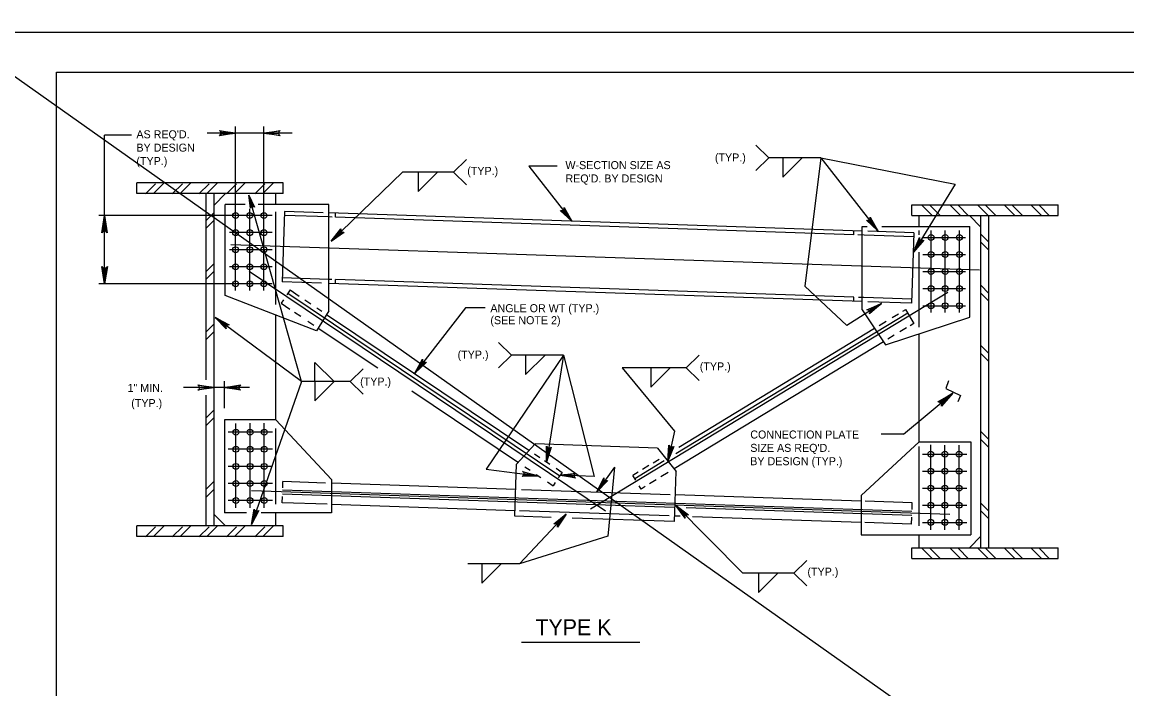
# Model space of a CAD drawing. Extents: x 634656 to 641360, y 298715 to 301183.
# Drawn here: x 635534.5 to 635948.6, y 300260.9 to 300510.8 of the extents above; entities that cross this region are included whole.
import ezdxf

# ---------------------------------------------------------------- set-up
doc = ezdxf.new("R2010")
doc.units = 0
for name, color, linetype in [('1', 7, 'Continuous'), ('2', 7, 'Continuous'), ('PLT-BNDY', 7, 'Continuous')]:
    doc.layers.add(name, color=color, linetype=linetype)

msp = doc.modelspace()

# ---------------------------------------------------------------- linework, layer by layer
at = {"layer": '1'}
for p, q in [((635502.92, 300510.77), (636362.53, 299902.94)), ((635614.56, 300410.14), (635614.56, 300471.64)), ((635625.18, 300410.14), (635625.18, 300471.64)), ((635565.46, 300438.26), (635565.46, 300468.36)), ((635833.84, 300459.87), (635814.41, 300459.87)), ((635833.84, 300459.87), (635827.91, 300411.87)), ((635833.84, 300459.87), (635855.28, 300432.5)), ((635833.84, 300459.87), (635884.2, 300450.08)), ((635677.12, 300454.5), (635650.4, 300428.64)), ((635724.42, 300456.73), (635740.53, 300436.16)), ((635632.4, 300450.49), (635577.59, 300450.49)), ((635577.59, 300446.49), (635577.59, 300450.49)), ((635584.56, 300450.21), (635580.75, 300446.4)), ((635587.76, 300450.49), (635583.77, 300446.49)), ((635594.6, 300450.21), (635590.78, 300446.4)), ((635597.8, 300450.49), (635593.8, 300446.49)), ((635604.63, 300450.21), (635600.82, 300446.4)), ((635607.83, 300450.49), (635603.83, 300446.49)), ((635614.9, 300450.21), (635611.09, 300446.4)), ((635618.1, 300450.49), (635614.11, 300446.49)), ((635625.51, 300450.21), (635621.7, 300446.4)), ((635628.71, 300450.49), (635624.71, 300446.49)), ((635632.4, 300446.49), (635632.4, 300450.49)), ((635884.2, 300450.08), (635868.61, 300424.55)), ((635632.4, 300446.49), (635577.59, 300446.49)), ((635603.5, 300376.66), (635603.5, 300446.49)), ((635606.5, 300321.96), (635606.5, 300446.49)), ((635606.5, 300442.17), (635610.82, 300446.49)), ((635639.27, 300376.12), (635619.55, 300445.94)), ((635629.64, 300442.37), (635629.64, 300446.49)), ((635610.61, 300408.38), (635610.61, 300442.37)), ((635618.17, 300442.37), (635610.61, 300442.37)), ((635649.52, 300442.37), (635623.07, 300442.37)), ((635649.52, 300402.59), (635649.52, 300442.37)), ((635867.97, 300442.3), (635922.79, 300442.3)), ((635867.97, 300438.3), (635867.97, 300442.3)), ((635871.67, 300442.3), (635875.66, 300438.3)), ((635874.87, 300442.02), (635878.68, 300438.21)), ((635882.27, 300442.3), (635886.27, 300438.3)), ((635885.47, 300442.02), (635889.28, 300438.21)), ((635892.54, 300442.3), (635896.54, 300438.3)), ((635895.75, 300442.02), (635899.56, 300438.21)), ((635902.58, 300442.3), (635906.57, 300438.3)), ((635905.78, 300442.02), (635909.59, 300438.21)), ((635912.61, 300442.3), (635916.61, 300438.3)), ((635915.81, 300442.02), (635919.62, 300438.21)), ((635922.79, 300438.3), (635922.79, 300442.3)), ((635628.31, 300438.26), (635563.35, 300438.26)), ((635565.46, 300412.69), (635565.46, 300438.26)), ((635606.5, 300439.46), (635603.5, 300436.46)), ((635619.87, 300410.14), (635619.87, 300440.82)), ((635629.64, 300404.98), (635629.64, 300439.65)), ((635632.85, 300439.81), (635631.95, 300413.44)), ((635649.36, 300437.75), (635632.8, 300438.31)), ((635647.41, 300439.32), (635632.85, 300439.81)), ((635650.72, 300437.71), (635649.36, 300437.75)), ((635849.34, 300432.47), (635649.52, 300439.25)), ((635652.02, 300437.69), (635652.02, 300439.19)), ((635846.3, 300431.07), (635652.02, 300437.66)), ((635867.97, 300438.3), (635922.79, 300438.3)), ((635870.74, 300434.18), (635870.74, 300438.3)), ((635893.88, 300433.97), (635889.55, 300438.3)), ((635893.88, 300313.77), (635893.88, 300438.3)), ((635896.88, 300313.77), (635896.88, 300438.3)), ((635606.5, 300436.53), (635603.5, 300433.53)), ((635849.34, 300402.89), (635849.34, 300434.18)), ((635849.34, 300434.18), (635851.31, 300434.18)), ((635856.7, 300434.18), (635889.77, 300434.18)), ((635889.77, 300400.19), (635889.77, 300434.18)), ((635628.31, 300431.87), (635612.21, 300431.87)), ((635846.3, 300431.07), (635846.3, 300432.53)), ((635850.08, 300430.94), (635847.77, 300431.02)), ((635868.74, 300430.31), (635850.08, 300430.94)), ((635868.79, 300431.81), (635851.52, 300432.39)), ((635868.79, 300431.81), (635867.9, 300405.44)), ((635870.74, 300431.01), (635870.74, 300432.71)), ((635872.06, 300430.07), (635888.16, 300430.07)), ((635875.2, 300401.95), (635875.2, 300432.63)), ((635880.51, 300401.95), (635880.51, 300432.63)), ((635885.82, 300401.95), (635885.82, 300432.63)), ((635893.88, 300431.27), (635896.88, 300428.26)), ((635628.31, 300425.48), (635612.21, 300425.48)), ((635893.32, 300417.78), (635612.8, 300427.29)), ((635870.74, 300396.42), (635870.74, 300424.62)), ((635893.88, 300428.34), (635896.88, 300425.34)), ((635872.06, 300423.68), (635888.16, 300423.68)), ((635606.5, 300420.33), (635603.5, 300417.33)), ((635606.5, 300417.41), (635603.5, 300414.4)), ((635628.31, 300419.08), (635612.21, 300419.08)), ((635619.62, 300417.49), (635753.2, 300327.64)), ((635872.06, 300417.28), (635888.16, 300417.28)), ((635628.31, 300412.69), (635563.35, 300412.69)), ((635646.76, 300412.94), (635631.95, 300413.44)), ((635649.52, 300414.35), (635632, 300414.94)), ((635650.56, 300414.31), (635649.52, 300414.35)), ((635849.34, 300406.07), (635649.52, 300412.85)), ((635652.02, 300412.79), (635652.02, 300414.29)), ((635846.3, 300407.67), (635652.02, 300414.26)), ((635893.88, 300412.14), (635896.88, 300409.13)), ((635644.84, 300395.07), (635610.61, 300408.38)), ((635634.97, 300410.43), (635633.75, 300408.6)), ((635634.13, 300409.17), (635736.05, 300340.8)), ((635634.97, 300410.43), (635638.43, 300408.11)), ((635881.52, 300409.5), (635747.6, 300328.2)), ((635827.91, 300411.87), (635843.58, 300397.05)), ((635872.06, 300410.89), (635888.16, 300410.89)), ((635893.88, 300409.21), (635896.88, 300406.21)), ((635632.5, 300406.74), (635631.63, 300405.44)), ((635631.63, 300405.44), (635634.88, 300403.26)), ((635640.48, 300406.73), (635642.79, 300405.18)), ((635856.6, 300405.3), (635843.58, 300397.05)), ((635846.3, 300406.13), (635846.3, 300407.67)), ((635850.04, 300407.54), (635848.06, 300407.61)), ((635867.95, 300406.94), (635850.04, 300407.54)), ((635867.9, 300405.44), (635851.51, 300405.99)), ((635872.06, 300404.5), (635888.16, 300404.5)), ((635639.27, 300376.12), (635606.87, 300400.04)), ((635629.64, 300361.72), (635629.64, 300400.98)), ((635636.67, 300402.06), (635638.96, 300400.53)), ((635649.52, 300402.59), (635644.84, 300395.07)), ((635644.99, 300403.71), (635646.93, 300402.41)), ((635648.67, 300401.22), (635724.47, 300350.38)), ((635700.69, 300403.7), (635681.78, 300379.28)), ((635866.46, 300401.73), (635779.6, 300349.01)), ((635849.34, 300402.89), (635858.17, 300389.82)), ((635858.17, 300389.82), (635889.77, 300400.19)), ((635863.01, 300401.39), (635860.64, 300399.96)), ((635865.64, 300402.99), (635864.49, 300402.29)), ((635865.62, 300403.12), (635868.8, 300397.89)), ((635606.5, 300397.75), (635603.5, 300394.74)), ((635641.66, 300398.72), (635643.83, 300397.26)), ((635645.5, 300396.12), (635667.8, 300381.17)), ((635854.04, 300395.95), (635780.61, 300351.37)), ((635858.37, 300398.58), (635855.76, 300397)), ((635865.96, 300396.17), (635863.51, 300394.68)), ((635868.8, 300397.89), (635867.34, 300397)), ((635606.5, 300394.82), (635603.5, 300391.82)), ((635861.41, 300393.4), (635859.05, 300391.97)), ((635870.74, 300353.53), (635870.74, 300393.95)), ((635857.4, 300390.97), (635778.92, 300343.33)), ((635893.88, 300389.55), (635896.88, 300386.55)), ((635737.41, 300385.99), (635708.43, 300343.23)), ((635737.41, 300385.99), (635717.98, 300385.99)), ((635737.41, 300385.99), (635731.11, 300345.92)), ((635737.41, 300385.99), (635748.96, 300340.44)), ((635893.88, 300386.63), (635896.88, 300383.63)), ((635759.48, 300381.23), (635779.02, 300357.46)), ((635610.33, 300366.16), (635610.33, 300376.26)), ((635603.5, 300321.96), (635603.5, 300370.94)), ((635680.56, 300372.6), (635720.52, 300345.8)), ((635864.81, 300356.4), (635883.4, 300371.78)), ((635606.5, 300365.54), (635603.5, 300362.54)), ((635606.5, 300362.61), (635603.5, 300359.61)), ((635610.33, 300361.72), (635610.33, 300326.86)), ((635629.64, 300361.72), (635610.33, 300361.72)), ((635614.68, 300328.75), (635614.68, 300360.4)), ((635619.99, 300328.75), (635619.99, 300360.47)), ((635625.3, 300328.75), (635625.3, 300360.54)), ((635629.64, 300361.72), (635650.48, 300339.34)), ((635629.64, 300330.16), (635629.64, 300358.49)), ((635628.44, 300357.08), (635611.72, 300357.08)), ((635779.02, 300357.46), (635776.59, 300346.3)), ((635864.81, 300356.4), (635856.5, 300356.4)), ((635893.88, 300357.35), (635896.88, 300354.34)), ((635893.88, 300354.42), (635896.88, 300351.42)), ((635628.44, 300350.69), (635611.72, 300350.69)), ((635726.81, 300352.68), (635719.86, 300345.08)), ((635772.71, 300351.12), (635726.81, 300352.68)), ((635772.71, 300351.12), (635779.64, 300342.43)), ((635870.74, 300353.53), (635848.98, 300333.36)), ((635870.74, 300353.53), (635890.04, 300353.53)), ((635870.74, 300321.97), (635870.74, 300351.75)), ((635875.08, 300320.56), (635875.08, 300352.35)), ((635880.39, 300320.56), (635880.39, 300352.28)), ((635885.7, 300320.56), (635885.7, 300352.21)), ((635890.04, 300353.53), (635890.04, 300318.67)), ((635726.59, 300348.95), (635728.57, 300347.63)), ((635730.31, 300346.46), (635732.34, 300345.1)), ((635775.2, 300346.34), (635764.15, 300339.63)), ((635773.27, 300346.92), (635771.02, 300345.55)), ((635871.93, 300348.89), (635888.66, 300348.89)), ((635628.44, 300344.29), (635611.72, 300344.29)), ((635708.43, 300343.23), (635727.81, 300340.77)), ((635719.2, 300325.64), (635719.86, 300345.08)), ((635723, 300344.14), (635724.95, 300342.83)), ((635734.64, 300343.56), (635736.89, 300342.05)), ((635736.89, 300342.05), (635735.49, 300339.96)), ((635756.51, 300344.02), (635749.96, 300334.77)), ((635756.51, 300344.02), (635754.11, 300318.2)), ((635765.37, 300342.12), (635763.37, 300340.91)), ((635769.42, 300344.58), (635767.01, 300343.12)), ((635776.68, 300341.97), (635773.97, 300340.33)), ((635779.01, 300323.61), (635779.64, 300342.43)), ((635871.93, 300342.49), (635888.66, 300342.49)), ((635606.5, 300338.7), (635603.5, 300335.7)), ((635628.44, 300337.9), (635611.72, 300337.9)), ((635632.2, 300336.31), (635632.28, 300338.6)), ((635648.3, 300338.06), (635632.28, 300338.6)), ((635650.48, 300339.34), (635650.48, 300326.86)), ((635719.54, 300335.64), (635650.48, 300337.98)), ((635727.21, 300341.31), (635728.96, 300340.14)), ((635731.44, 300338.48), (635733.55, 300337.06)), ((635734.32, 300338.22), (635733.55, 300337.06)), ((635748.96, 300340.44), (635736.22, 300341.05)), ((635764.49, 300339.08), (635763.37, 300340.91)), ((635772.12, 300339.2), (635769.72, 300337.74)), ((635606.5, 300335.78), (635603.5, 300332.78)), ((635882.27, 300326.25), (635620.46, 300335.13)), ((635778.92, 300328.91), (635632.12, 300333.89)), ((635868.04, 300327.35), (635632.17, 300335.36)), ((635777.45, 300333.67), (635721.75, 300335.56)), ((635766.49, 300335.79), (635765.77, 300336.97)), ((635768.07, 300336.74), (635766.49, 300335.79)), ((635848.98, 300331.25), (635779.34, 300333.61)), ((635871.93, 300336.1), (635888.66, 300336.1)), ((635628.44, 300331.51), (635611.72, 300331.51)), ((635632.01, 300330.64), (635632.09, 300332.95)), ((635648.93, 300330.07), (635632.01, 300330.64)), ((635719.27, 300327.68), (635650.48, 300330.02)), ((635779.52, 300329.62), (635804.62, 300304.32)), ((635848.98, 300333.36), (635848.98, 300318.67)), ((635868.15, 300330.6), (635850.46, 300331.2)), ((635868.06, 300328.12), (635868.15, 300330.6)), ((635871.93, 300329.71), (635888.66, 300329.71)), ((635893.88, 300330.51), (635896.88, 300327.51)), ((635606.5, 300326.29), (635610.82, 300321.96)), ((635618.62, 300326.86), (635610.33, 300326.86)), ((635650.48, 300326.86), (635624.16, 300326.86)), ((635629.64, 300321.96), (635629.64, 300326.86)), ((635732.8, 300325.18), (635719.2, 300325.64)), ((635777.05, 300325.72), (635720.9, 300327.63)), ((635721, 300307.81), (635738.47, 300326.4)), ((635781.14, 300325.58), (635779.07, 300325.65)), ((635867.99, 300325.88), (635783.36, 300328.75)), ((635848.98, 300323.28), (635785.77, 300325.43)), ((635867.88, 300322.64), (635867.96, 300325.23)), ((635893.88, 300327.59), (635896.88, 300324.59)), ((635632.4, 300321.96), (635577.59, 300321.96)), ((635577.59, 300317.96), (635577.59, 300321.96)), ((635584.56, 300321.68), (635580.75, 300317.87)), ((635587.76, 300321.96), (635583.77, 300317.96)), ((635594.6, 300321.68), (635590.78, 300317.87)), ((635597.8, 300321.96), (635593.8, 300317.96)), ((635604.63, 300321.68), (635600.82, 300317.87)), ((635607.83, 300321.96), (635603.83, 300317.96)), ((635614.9, 300321.68), (635611.09, 300317.87)), ((635618.1, 300321.96), (635614.11, 300317.96)), ((635625.51, 300321.68), (635621.7, 300317.87)), ((635628.71, 300321.96), (635624.71, 300317.96)), ((635632.4, 300317.96), (635632.4, 300321.96)), ((635779.01, 300323.61), (635740.75, 300324.91)), ((635867.88, 300322.64), (635850.34, 300323.24)), ((635871.93, 300323.32), (635888.66, 300323.32)), ((635632.4, 300317.96), (635577.59, 300317.96)), ((635754.11, 300318.2), (635721, 300307.81)), ((635848.98, 300318.67), (635890.04, 300318.67)), ((635870.74, 300313.77), (635870.74, 300318.67)), ((635893.88, 300318.1), (635889.55, 300313.77)), ((635867.97, 300313.77), (635922.79, 300313.77)), ((635867.97, 300309.77), (635867.97, 300313.77)), ((635871.67, 300313.77), (635875.66, 300309.77)), ((635874.87, 300313.49), (635878.68, 300309.68)), ((635882.27, 300313.77), (635886.27, 300309.77)), ((635885.47, 300313.49), (635889.28, 300309.68)), ((635892.54, 300313.77), (635896.54, 300309.77)), ((635895.75, 300313.49), (635899.56, 300309.68)), ((635902.58, 300313.77), (635906.57, 300309.77)), ((635905.78, 300313.49), (635909.59, 300309.68)), ((635912.61, 300313.77), (635916.61, 300309.77)), ((635915.81, 300313.49), (635919.62, 300309.68)), ((635922.79, 300309.77), (635922.79, 300313.77)), ((635867.97, 300309.77), (635922.79, 300309.77)), ((635721, 300307.81), (635701.57, 300307.81))]:
    msp.add_line(p, q, dxfattribs=at)
for points in [[(635608.76, 300469.89), (635608.98, 300469.47), (635614.56, 300469.16), (635608.76, 300469.89), (635608.46, 300470.15), (635614.56, 300469.16), (635608.98, 300468.89), (635608.78, 300468.47), (635614.56, 300469.16), (635608.46, 300468.19), (635608.78, 300468.47)], [(635630.98, 300468.44), (635630.76, 300468.86), (635625.18, 300469.16), (635630.98, 300468.44), (635631.27, 300468.18), (635625.18, 300469.16), (635630.76, 300469.44), (635630.96, 300469.85), (635625.18, 300469.16), (635631.27, 300470.13), (635630.96, 300469.85)], [(635620.24, 300441.34), (635620.52, 300441.59), (635619.55, 300445.94), (635620.24, 300441.34), (635620.11, 300441.06), (635619.55, 300445.94), (635620.96, 300441.72), (635621.33, 300441.66), (635619.55, 300445.94), (635621.61, 300441.48), (635621.33, 300441.66)], [(635737.66, 300440.95), (635737.48, 300440.54), (635740.53, 300436.16), (635737.66, 300440.95), (635737.68, 300441.32), (635740.53, 300436.16), (635737.04, 300440.19), (635736.61, 300440.1), (635740.53, 300436.16), (635736.21, 300440.17), (635736.61, 300440.1)], [(635564.69, 300432.13), (635565.13, 300432.36), (635565.46, 300438.26), (635564.69, 300432.13), (635564.42, 300431.81), (635565.46, 300438.26), (635565.75, 300432.36), (635566.19, 300432.15), (635565.46, 300438.26), (635566.48, 300431.81), (635566.19, 300432.15)], [(635852.42, 300437.28), (635852.23, 300436.87), (635855.28, 300432.5), (635852.42, 300437.28), (635852.43, 300437.66), (635855.28, 300432.5), (635851.79, 300436.53), (635851.36, 300436.43), (635855.28, 300432.5), (635850.97, 300436.51), (635851.36, 300436.43)], [(635654.93, 300431.91), (635654.5, 300432.06), (635650.4, 300428.64), (635654.93, 300431.91), (635655.3, 300431.92), (635650.4, 300428.64), (635654.12, 300432.46), (635653.99, 300432.89), (635650.4, 300428.64), (635654.03, 300433.28), (635653.99, 300432.89)], [(635872.09, 300428.91), (635871.64, 300428.95), (635868.61, 300424.55), (635872.09, 300428.91), (635872.44, 300429.03), (635868.61, 300424.55), (635871.16, 300429.23), (635870.92, 300429.61), (635868.61, 300424.55), (635870.85, 300430), (635870.92, 300429.61)], [(635566.23, 300418.82), (635565.78, 300418.59), (635565.46, 300412.69), (635566.23, 300418.82), (635566.49, 300419.14), (635565.46, 300412.69), (635565.16, 300418.59), (635564.73, 300418.8), (635565.46, 300412.69), (635564.43, 300419.14), (635564.73, 300418.8)], [(635851.55, 300402.92), (635851.94, 300402.69), (635856.6, 300405.3), (635851.55, 300402.92), (635851.18, 300402.97), (635856.6, 300405.3), (635852.24, 300402.22), (635852.29, 300401.78), (635856.6, 300405.3), (635852.18, 300401.4), (635852.29, 300401.78)], [(635610.91, 300396.19), (635610.98, 300396.64), (635606.87, 300400.04), (635610.91, 300396.19), (635610.99, 300395.83), (635606.87, 300400.04), (635611.31, 300397.09), (635611.7, 300397.29), (635606.87, 300400.04), (635612.1, 300397.33), (635611.7, 300397.29)], [(635685.73, 300383.22), (635685.28, 300383.3), (635681.78, 300379.28), (635685.73, 300383.22), (635686.09, 300383.29), (635681.78, 300379.28), (635684.84, 300383.64), (635684.65, 300384.04), (635681.78, 300379.28), (635684.62, 300384.44), (635684.65, 300384.04)], [(635600.7, 300374.55), (635600.91, 300374.13), (635606.5, 300373.82), (635600.7, 300374.55), (635600.4, 300374.81), (635606.5, 300373.82), (635600.92, 300373.55), (635600.71, 300373.13), (635606.5, 300373.82), (635600.4, 300372.85), (635600.71, 300373.13)], [(635881.79, 300376.29), (635880.79, 300373.49), (635886.2, 300370.88), (635885.2, 300368.47)], [(635616.13, 300373.09), (635615.91, 300373.51), (635610.33, 300373.82), (635616.13, 300373.09), (635616.43, 300372.84), (635610.33, 300373.82), (635615.91, 300374.1), (635616.11, 300374.51), (635610.33, 300373.82), (635616.43, 300374.79), (635616.11, 300374.51)], [(635878.18, 300368.47), (635878.64, 300368.27), (635883.4, 300371.78), (635878.18, 300368.47), (635877.77, 300368.47), (635883.4, 300371.78), (635879.04, 300367.8), (635879.15, 300367.32), (635883.4, 300371.78), (635879.08, 300366.88), (635879.15, 300367.32)], [(635732.6, 300351.3), (635732.18, 300351.15), (635731.11, 300345.92), (635732.6, 300351.3), (635732.88, 300351.54), (635731.11, 300345.92), (635731.62, 300351.23), (635731.26, 300351.48), (635731.11, 300345.92), (635731.04, 300351.81), (635731.26, 300351.48)], [(635778.44, 300351.56), (635778.01, 300351.45), (635776.59, 300346.3), (635778.44, 300351.56), (635778.74, 300351.79), (635776.59, 300346.3), (635777.46, 300351.56), (635777.12, 300351.83), (635776.59, 300346.3), (635776.92, 300352.18), (635777.12, 300351.83)], [(635722.39, 300342.09), (635722.55, 300341.67), (635727.81, 300340.77), (635722.39, 300342.09), (635722.13, 300342.36), (635727.81, 300340.77), (635722.49, 300341.11), (635722.25, 300340.74), (635727.81, 300340.77), (635721.92, 300340.51), (635722.25, 300340.74)], [(635741.71, 300340.09), (635741.53, 300340.5), (635736.22, 300341.05), (635741.71, 300340.09), (635741.99, 300339.83), (635736.22, 300341.05), (635741.55, 300341.06), (635741.76, 300341.44), (635736.22, 300341.05), (635742.08, 300341.69), (635741.76, 300341.44)], [(635753.73, 300338.88), (635753.28, 300338.95), (635749.96, 300334.77), (635753.73, 300338.88), (635754.09, 300338.97), (635749.96, 300334.77), (635752.82, 300339.26), (635752.61, 300339.65), (635749.96, 300334.77), (635752.57, 300340.05), (635752.61, 300339.65)], [(635782.95, 300325.23), (635783.09, 300325.65), (635779.52, 300329.62), (635782.95, 300325.23), (635782.98, 300324.85), (635779.52, 300329.62), (635783.48, 300326.05), (635783.9, 300326.2), (635779.52, 300329.62), (635784.29, 300326.17), (635783.9, 300326.2)], [(635622.96, 300327.51), (635622.51, 300327.45), (635620.47, 300322.51), (635622.96, 300327.51), (635623.28, 300327.7), (635620.47, 300322.51), (635621.98, 300327.63), (635621.67, 300327.94), (635620.47, 300322.51), (635621.52, 300328.31), (635621.67, 300327.94)], [(635734.17, 300322.84), (635734.61, 300322.72), (635738.47, 300326.4), (635734.17, 300322.84), (635733.8, 300322.8), (635738.47, 300326.4), (635735.02, 300322.34), (635735.17, 300321.92), (635738.47, 300326.4), (635735.16, 300321.52), (635735.17, 300321.92)]]:
    msp.add_lwpolyline(points, dxfattribs=at)
for centre in [(635614.56, 300438.26), (635619.87, 300438.26), (635625.18, 300438.26), (635614.56, 300431.87), (635619.87, 300431.87), (635625.18, 300431.87), (635875.2, 300430.07), (635880.51, 300430.07), (635885.82, 300430.07), (635614.56, 300425.48), (635619.87, 300425.48), (635625.18, 300425.48), (635875.2, 300423.68), (635880.51, 300423.68), (635885.82, 300423.68), (635614.56, 300419.08), (635619.87, 300419.08), (635625.18, 300419.08), (635875.2, 300417.28), (635880.51, 300417.28), (635885.82, 300417.28), (635614.56, 300412.69), (635619.87, 300412.69), (635625.18, 300412.69), (635875.2, 300410.89), (635880.51, 300410.89), (635885.82, 300410.89), (635875.2, 300404.5), (635880.51, 300404.5), (635885.82, 300404.5), (635614.68, 300357.08), (635619.99, 300357.08), (635625.3, 300357.08), (635614.68, 300350.69), (635619.99, 300350.69), (635625.3, 300350.69), (635875.08, 300348.89), (635880.39, 300348.89), (635885.7, 300348.89), (635614.68, 300344.29), (635619.99, 300344.29), (635625.3, 300344.29), (635875.08, 300342.49), (635880.39, 300342.49), (635885.7, 300342.49), (635614.68, 300337.9), (635619.99, 300337.9), (635625.3, 300337.9), (635875.08, 300336.1), (635880.39, 300336.1), (635885.7, 300336.1), (635614.68, 300331.51), (635619.99, 300331.51), (635625.3, 300331.51), (635875.08, 300329.71), (635880.39, 300329.71), (635885.7, 300329.71), (635875.08, 300323.32), (635880.39, 300323.32), (635885.7, 300323.32)]:
    msp.add_circle(centre, 1.09, dxfattribs=at)
at = {"layer": '2'}
for p, q in [((635547.42, 299927.99), (635547.42, 300491.99)), ((635547.42, 300491.99), (636333.42, 300491.99)), ((635575.48, 300468.36), (635565.46, 300468.36)), ((635614.56, 300469.16), (635603.94, 300469.16)), ((635625.18, 300469.16), (635614.56, 300469.16)), ((635635.79, 300469.16), (635625.18, 300469.16)), ((635819.69, 300459.87), (635819.69, 300452.62)), ((635819.69, 300452.62), (635826.94, 300459.87)), ((635696.24, 300454.5), (635677.12, 300454.5)), ((635682.99, 300454.5), (635682.99, 300447.25)), ((635682.99, 300447.25), (635690.24, 300454.5)), ((635735.12, 300456.73), (635724.42, 300456.73)), ((635708.05, 300403.7), (635700.69, 300403.7)), ((635723.26, 300385.99), (635723.26, 300378.74)), ((635723.26, 300378.74), (635730.51, 300385.99)), ((635783.39, 300381.23), (635759.48, 300381.23)), ((635770.14, 300381.23), (635770.14, 300373.98)), ((635770.14, 300373.98), (635777.39, 300381.23)), ((635639.27, 300376.12), (635620.47, 300322.51)), ((635657.51, 300376.12), (635639.27, 300376.12)), ((635644.26, 300376.12), (635644.26, 300368.87)), ((635644.26, 300368.87), (635651.51, 300376.12)), ((635606.5, 300373.82), (635595.04, 300373.82)), ((635610.33, 300373.82), (635606.5, 300373.82)), ((635619.73, 300373.82), (635610.33, 300373.82)), ((635706.85, 300307.81), (635706.85, 300300.56)), ((635706.85, 300300.56), (635714.1, 300307.81)), ((635823.74, 300304.32), (635804.62, 300304.32)), ((635810.49, 300304.32), (635810.49, 300297.07)), ((635810.49, 300297.07), (635817.74, 300304.32)), ((635766.1, 300278.24), (635721.73, 300278.24))]:
    msp.add_line(p, q, dxfattribs=at)
for points in [[(635809.54, 300464.62), (635814.41, 300459.87), (635809.54, 300455.12)], [(635701.11, 300459.25), (635696.24, 300454.5), (635701.11, 300449.75)], [(635713.1, 300390.74), (635717.98, 300385.99), (635713.1, 300381.24)], [(635644.26, 300376.12), (635644.26, 300383.24), (635651.51, 300376.12), (635644.26, 300376.12)], [(635788.27, 300385.98), (635783.39, 300381.23), (635788.27, 300376.48)], [(635662.38, 300380.87), (635657.51, 300376.12), (635662.38, 300371.37)], [(635828.61, 300309.07), (635823.74, 300304.32), (635828.61, 300299.57)]]:
    msp.add_lwpolyline(points, dxfattribs=at)
at = {"layer": 'PLT-BNDY'}
msp.add_lwpolyline([(635507.42, 300506.99), (636348.42, 300506.99), (636348.42, 299912.99), (635507.42, 299912.99)], close=True, dxfattribs=at)

# ---------------------------------------------------------------- texts
at = {"layer": '1'}
for s, height, p in [("AS REQ'D.", 3, (635577.38, 300467.23)), ('BY DESIGN', 3, (635577.38, 300462.23)), ('(TYP.)', 3, (635577.38, 300457.23)), ('ANGLE OR WT (TYP.)', 2.9999, (635710.04, 300402.07)), ('(SEE NOTE 2)', 2.9999, (635710.04, 300397.57)), ('1" MIN.', 3, (635574.06, 300372.19)), ('CONNECTION PLATE', 2.9999, (635807.44, 300354.73)), ("SIZE AS REQ'D.", 2.9999, (635807.44, 300349.73)), ('BY DESIGN (TYP.)', 2.9999, (635807.44, 300344.73))]:
    msp.add_text(s, height=height, dxfattribs=at).set_placement(p)
at = {"layer": '2'}
for s, height, p in [('W-SECTION SIZE AS', 2.9999, (635738.16, 300455.68)), ('(TYP.)', 3, (635794.19, 300458.55)), ('(TYP.)', 3, (635701.37, 300453.53)), ("REQ'D. BY DESIGN", 2.9999, (635738.16, 300450.68)), ('(TYP.)', 3, (635697.76, 300384.67)), ('(TYP.)', 3, (635788.52, 300380.25)), ('(TYP.)', 3, (635661.22, 300374.58)), ('(TYP.)', 3, (635575.44, 300366.51)), ('(TYP.)', 3, (635828.87, 300303.34)), ('TYPE K', 6, (635726.9, 300281.02))]:
    msp.add_text(s, height=height, dxfattribs=at).set_placement(p)

doc.saveas('drawing.dxf')
